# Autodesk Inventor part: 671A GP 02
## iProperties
Author: Charles Bliss
Shininess: 41.0
Angle Display Precision: 2
Document Length Units: 11272
Document Angle Units: 11286
Document Time Units: 11279
Document Mass Units: 11290
Document Length Units Precision: 5
Document Angle Units Precision: 2
Compacted: True
PropertySet Name: _Private Model Information
Created: 2002-02
Part Number: 671A GP 02
Document SubType Name: Modeling
Designer: Charles Bliss
Control State: 0
Master: False
Checked Out: False
PropertySet Name: Design Tracking Control
Density: 0.0
Volumn: 0.0
Area: 0.0
PropertySet Name: Model Information
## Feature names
1. Extrusion1
2. Extrusion2
3. Fillet1
4. Fillet2
5. Revolution1
6. ScrewSlot [Extrusion]
7. RingPad [Extrusion]
8. SqrPad [Extrusion]
9. Extrusion6
10. MtgHole2 [Extrusion]
11. Mirror1
12. Rectangular Pattern1
13. TermPattern [Rectangular Pattern]
